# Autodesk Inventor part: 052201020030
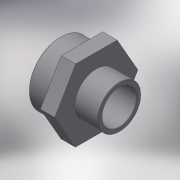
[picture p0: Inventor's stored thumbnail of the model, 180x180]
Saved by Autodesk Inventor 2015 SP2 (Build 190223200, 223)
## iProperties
Created: 2017-10
Part Number: 052201020030
Material: Generic
Description: PLASSON SOCKET NIPPLE THR. P 2"-3"
Document SubType Name: Modeling
Designer: KIM
Density: 1 g/cm^3
Appearance: Default
Author: KIM
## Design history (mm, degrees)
derived "052201.ipt"
feature "Solid1::052201.ipt"
tag "TaggingFeature1"
body "Solid1"
other parameters: "d2" = 95, "d13" = 0, "d14" = 0.84926, "d17" = 26, "d18" = 39.6, "d19" = 94.39525, "d20" = 84.926, "d21" = 59.614, "d22" = 20.8, "d23" = 80.6797, "d24" = 47.6912, "d25" = 33, "d26" = -26, "G_" = 84.926, "R_" = 59.614, "C_" = 95, "lt_1" = 26, "lt_" = 33
